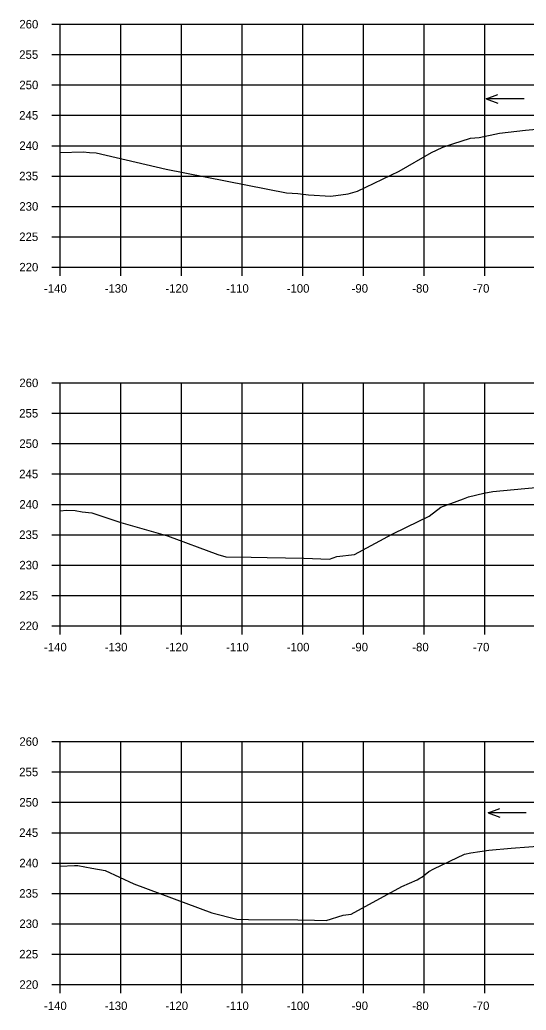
# Model space of a CAD drawing. Extents: x 1342547 to 1344156, y -1532351 to -1517216.
# Drawn here: x 1342556.2 to 1342639.7, y -1526792.6 to -1526629.6 of the extents above; entities that cross this region are included whole.
import ezdxf

# ---------------------------------------------------------------- set-up
doc = ezdxf.new("R2010")
doc.units = 0
for name, color, linetype in [('R_Axis', 7, 'Continuous'), ('R_Axis Annot', 7, 'Continuous'), ('R_Exist Surface', 7, 'Continuous'), ('R_Grid', 7, 'Continuous'), ('R_Water', 7, 'Continuous')]:
    doc.layers.add(name, color=color, linetype=linetype)

msp = doc.modelspace()

# ---------------------------------------------------------------- linework, layer by layer
at = {"layer": 'R_Axis'}
for p, q in [((1342561.47, -1526630.31), (1342562.87, -1526630.31)), ((1342562.87, -1526670.31), (1342562.87, -1526630.31)), ((1342561.47, -1526635.31), (1342562.87, -1526635.31)), ((1342561.47, -1526640.31), (1342562.87, -1526640.31)), ((1342561.47, -1526645.31), (1342562.87, -1526645.31)), ((1342561.47, -1526650.31), (1342562.87, -1526650.31)), ((1342561.47, -1526655.31), (1342562.87, -1526655.31)), ((1342561.47, -1526660.31), (1342562.87, -1526660.31)), ((1342561.47, -1526665.31), (1342562.87, -1526665.31)), ((1342561.47, -1526670.31), (1342562.87, -1526670.31)), ((1342562.87, -1526670.31), (1342842.87, -1526670.31)), ((1342562.87, -1526671.71), (1342562.87, -1526670.31)), ((1342572.87, -1526671.71), (1342572.87, -1526670.31)), ((1342582.87, -1526671.71), (1342582.87, -1526670.31)), ((1342592.87, -1526671.71), (1342592.87, -1526670.31)), ((1342602.87, -1526671.71), (1342602.87, -1526670.31)), ((1342612.87, -1526671.71), (1342612.87, -1526670.31)), ((1342622.87, -1526671.71), (1342622.87, -1526670.31)), ((1342632.87, -1526671.71), (1342632.87, -1526670.31)), ((1342561.47, -1526689.36), (1342562.87, -1526689.36)), ((1342562.87, -1526729.36), (1342562.87, -1526689.36)), ((1342561.47, -1526694.36), (1342562.87, -1526694.36)), ((1342561.47, -1526699.36), (1342562.87, -1526699.36)), ((1342561.47, -1526704.36), (1342562.87, -1526704.36)), ((1342561.47, -1526709.36), (1342562.87, -1526709.36)), ((1342561.47, -1526714.36), (1342562.87, -1526714.36)), ((1342561.47, -1526719.36), (1342562.87, -1526719.36)), ((1342561.47, -1526724.36), (1342562.87, -1526724.36)), ((1342561.47, -1526729.36), (1342562.87, -1526729.36)), ((1342562.87, -1526729.36), (1342842.87, -1526729.36)), ((1342562.87, -1526730.76), (1342562.87, -1526729.36)), ((1342572.87, -1526730.76), (1342572.87, -1526729.36)), ((1342582.87, -1526730.76), (1342582.87, -1526729.36)), ((1342592.87, -1526730.76), (1342592.87, -1526729.36)), ((1342602.87, -1526730.76), (1342602.87, -1526729.36)), ((1342612.87, -1526730.76), (1342612.87, -1526729.36)), ((1342622.87, -1526730.76), (1342622.87, -1526729.36)), ((1342632.87, -1526730.76), (1342632.87, -1526729.36)), ((1342561.47, -1526748.41), (1342562.87, -1526748.41)), ((1342562.87, -1526788.41), (1342562.87, -1526748.41)), ((1342561.47, -1526753.41), (1342562.87, -1526753.41)), ((1342561.47, -1526758.41), (1342562.87, -1526758.41)), ((1342561.47, -1526763.41), (1342562.87, -1526763.41)), ((1342561.47, -1526768.41), (1342562.87, -1526768.41)), ((1342561.47, -1526773.41), (1342562.87, -1526773.41)), ((1342561.47, -1526778.41), (1342562.87, -1526778.41)), ((1342561.47, -1526783.41), (1342562.87, -1526783.41)), ((1342561.47, -1526788.41), (1342562.87, -1526788.41)), ((1342562.87, -1526788.41), (1342842.87, -1526788.41)), ((1342562.87, -1526789.81), (1342562.87, -1526788.41)), ((1342572.87, -1526789.81), (1342572.87, -1526788.41)), ((1342582.87, -1526789.81), (1342582.87, -1526788.41)), ((1342592.87, -1526789.81), (1342592.87, -1526788.41)), ((1342602.87, -1526789.81), (1342602.87, -1526788.41)), ((1342612.87, -1526789.81), (1342612.87, -1526788.41)), ((1342622.87, -1526789.81), (1342622.87, -1526788.41)), ((1342632.87, -1526789.81), (1342632.87, -1526788.41))]:
    msp.add_line(p, q, dxfattribs=at)
at = {"layer": 'R_Exist Surface'}
for points in [[(1342562.87, -1526651.46), (1342566.67, -1526651.33), (1342567.69, -1526651.44), (1342568.78, -1526651.5), (1342580.32, -1526654.18), (1342600.19, -1526658.07), (1342602.06, -1526658.19), (1342603.81, -1526658.39), (1342607.45, -1526658.6), (1342610.34, -1526658.25), (1342611.86, -1526657.79), (1342618.76, -1526654.5), (1342624.05, -1526651.45), (1342624.88, -1526651.06), (1342625.96, -1526650.55), (1342627.58, -1526650.03), (1342630.5, -1526649.07), (1342631.9, -1526648.96), (1342635.25, -1526648.26), (1342639.58, -1526647.77), (1342646.17, -1526647.13)], [(1342562.87, -1526710.4), (1342563.93, -1526710.33), (1342565.35, -1526710.38), (1342566.51, -1526710.58), (1342568.11, -1526710.77), (1342572.85, -1526712.34), (1342580.58, -1526714.56), (1342588.87, -1526717.64), (1342590.19, -1526717.98), (1342594.32, -1526718.07), (1342596.96, -1526718.09), (1342603.03, -1526718.2), (1342607.27, -1526718.36), (1342608.47, -1526717.97), (1342611.4, -1526717.63), (1342617.6, -1526714.25), (1342619.95, -1526713.12), (1342623.69, -1526711.32), (1342623.69, -1526711.32), (1342625.63, -1526709.81), (1342629.32, -1526708.47), (1342630.18, -1526708.11), (1342632.72, -1526707.49), (1342634.19, -1526707.26), (1342645.32, -1526706.18)], [(1342562.87, -1526768.91), (1342565.21, -1526768.83), (1342565.8, -1526768.84), (1342568.09, -1526769.24), (1342570.26, -1526769.65), (1342575.01, -1526771.83), (1342587.89, -1526776.6), (1342591.99, -1526777.65), (1342593.92, -1526777.69), (1342602.04, -1526777.77), (1342604.8, -1526777.82), (1342606.72, -1526777.89), (1342609.5, -1526776.98), (1342610.81, -1526776.83), (1342619.19, -1526772.26), (1342621.7, -1526771.18), (1342622.13, -1526770.92), (1342622.46, -1526770.73), (1342623.65, -1526769.8), (1342624.48, -1526769.35), (1342627.1, -1526768.11), (1342629.51, -1526766.95), (1342630.57, -1526766.75), (1342633.51, -1526766.29), (1342637.19, -1526765.94), (1342645.94, -1526765.31)]]:
    msp.add_lwpolyline(points, dxfattribs=at)
at = {"layer": 'R_Grid'}
for p, q in [((1342562.87, -1526630.31), (1342842.87, -1526630.31)), ((1342562.87, -1526670.31), (1342562.87, -1526630.31)), ((1342572.87, -1526670.31), (1342572.87, -1526630.31)), ((1342582.87, -1526670.31), (1342582.87, -1526630.31)), ((1342592.87, -1526670.31), (1342592.87, -1526630.31)), ((1342602.87, -1526670.31), (1342602.87, -1526630.31)), ((1342612.87, -1526670.31), (1342612.87, -1526630.31)), ((1342622.87, -1526670.31), (1342622.87, -1526630.31)), ((1342632.87, -1526670.31), (1342632.87, -1526630.31)), ((1342562.87, -1526635.31), (1342842.87, -1526635.31)), ((1342562.87, -1526640.31), (1342842.87, -1526640.31)), ((1342562.87, -1526645.31), (1342842.87, -1526645.31)), ((1342562.87, -1526650.31), (1342842.87, -1526650.31)), ((1342562.87, -1526655.31), (1342842.87, -1526655.31)), ((1342562.87, -1526660.31), (1342842.87, -1526660.31)), ((1342562.87, -1526665.31), (1342842.87, -1526665.31)), ((1342562.87, -1526670.31), (1342842.87, -1526670.31)), ((1342562.87, -1526689.36), (1342842.87, -1526689.36)), ((1342562.87, -1526729.36), (1342562.87, -1526689.36)), ((1342572.87, -1526729.36), (1342572.87, -1526689.36)), ((1342582.87, -1526729.36), (1342582.87, -1526689.36)), ((1342592.87, -1526729.36), (1342592.87, -1526689.36)), ((1342602.87, -1526729.36), (1342602.87, -1526689.36)), ((1342612.87, -1526729.36), (1342612.87, -1526689.36)), ((1342622.87, -1526729.36), (1342622.87, -1526689.36)), ((1342632.87, -1526729.36), (1342632.87, -1526689.36)), ((1342562.87, -1526694.36), (1342842.87, -1526694.36)), ((1342562.87, -1526699.36), (1342842.87, -1526699.36)), ((1342562.87, -1526704.36), (1342842.87, -1526704.36)), ((1342562.87, -1526709.36), (1342842.87, -1526709.36)), ((1342562.87, -1526714.36), (1342842.87, -1526714.36)), ((1342562.87, -1526719.36), (1342842.87, -1526719.36)), ((1342562.87, -1526724.36), (1342842.87, -1526724.36)), ((1342562.87, -1526729.36), (1342842.87, -1526729.36)), ((1342562.87, -1526748.41), (1342842.87, -1526748.41)), ((1342562.87, -1526788.41), (1342562.87, -1526748.41)), ((1342572.87, -1526788.41), (1342572.87, -1526748.41)), ((1342582.87, -1526788.41), (1342582.87, -1526748.41)), ((1342592.87, -1526788.41), (1342592.87, -1526748.41)), ((1342602.87, -1526788.41), (1342602.87, -1526748.41)), ((1342612.87, -1526788.41), (1342612.87, -1526748.41)), ((1342622.87, -1526788.41), (1342622.87, -1526748.41)), ((1342632.87, -1526788.41), (1342632.87, -1526748.41)), ((1342562.87, -1526753.41), (1342842.87, -1526753.41)), ((1342562.87, -1526758.41), (1342842.87, -1526758.41)), ((1342562.87, -1526763.41), (1342842.87, -1526763.41)), ((1342562.87, -1526768.41), (1342842.87, -1526768.41)), ((1342562.87, -1526773.41), (1342842.87, -1526773.41)), ((1342562.87, -1526778.41), (1342842.87, -1526778.41)), ((1342562.87, -1526783.41), (1342842.87, -1526783.41)), ((1342562.87, -1526788.41), (1342842.87, -1526788.41))]:
    msp.add_line(p, q, dxfattribs=at)
at = {"layer": 'R_Water'}
for p, q in [((1342633.08, -1526642.61), (1342635, -1526641.91)), ((1342639.36, -1526642.61), (1342633.08, -1526642.61)), ((1342633.08, -1526642.61), (1342635, -1526643.31)), ((1342633.39, -1526760.15), (1342635.31, -1526759.45)), ((1342639.68, -1526760.15), (1342633.39, -1526760.15)), ((1342633.39, -1526760.15), (1342635.31, -1526760.85))]:
    msp.add_line(p, q, dxfattribs=at)

# ---------------------------------------------------------------- texts
at = {"layer": 'R_Axis Annot'}
for s, p in [('260', (1342556.14, -1526631.01)), ('255', (1342556.12, -1526636.01)), ('250', (1342556.14, -1526641.01)), ('245', (1342556.12, -1526646.01)), ('240', (1342556.14, -1526651.01)), ('235', (1342556.12, -1526656.01)), ('230', (1342556.14, -1526661.01)), ('225', (1342556.12, -1526666.01)), ('220', (1342556.14, -1526671.01)), ('-140', (1342560.2, -1526674.51)), ('-130', (1342570.2, -1526674.51)), ('-120', (1342580.2, -1526674.51)), ('-110', (1342590.2, -1526674.51)), ('-100', (1342600.2, -1526674.51)), ('-90', (1342610.9, -1526674.51)), ('-80', (1342620.9, -1526674.51)), ('-70', (1342630.9, -1526674.51)), ('260', (1342556.14, -1526690.06)), ('255', (1342556.12, -1526695.06)), ('250', (1342556.14, -1526700.06)), ('245', (1342556.12, -1526705.06)), ('240', (1342556.14, -1526710.06)), ('235', (1342556.12, -1526715.06)), ('230', (1342556.14, -1526720.06)), ('225', (1342556.12, -1526725.06)), ('220', (1342556.14, -1526730.06)), ('-140', (1342560.2, -1526733.56)), ('-130', (1342570.2, -1526733.56)), ('-120', (1342580.2, -1526733.56)), ('-110', (1342590.2, -1526733.56)), ('-100', (1342600.2, -1526733.56)), ('-90', (1342610.9, -1526733.56)), ('-80', (1342620.9, -1526733.56)), ('-70', (1342630.9, -1526733.56)), ('260', (1342556.14, -1526749.11)), ('255', (1342556.12, -1526754.11)), ('250', (1342556.14, -1526759.11)), ('245', (1342556.12, -1526764.11)), ('240', (1342556.14, -1526769.11)), ('235', (1342556.12, -1526774.11)), ('230', (1342556.14, -1526779.11)), ('225', (1342556.12, -1526784.11)), ('220', (1342556.14, -1526789.11)), ('-140', (1342560.2, -1526792.61)), ('-130', (1342570.2, -1526792.61)), ('-120', (1342580.2, -1526792.61)), ('-110', (1342590.2, -1526792.61)), ('-100', (1342600.2, -1526792.61)), ('-90', (1342610.9, -1526792.61)), ('-80', (1342620.9, -1526792.61)), ('-70', (1342630.9, -1526792.61))]:
    msp.add_text(s, height=1.4, dxfattribs=at).set_placement(p)

doc.saveas('drawing.dxf')
